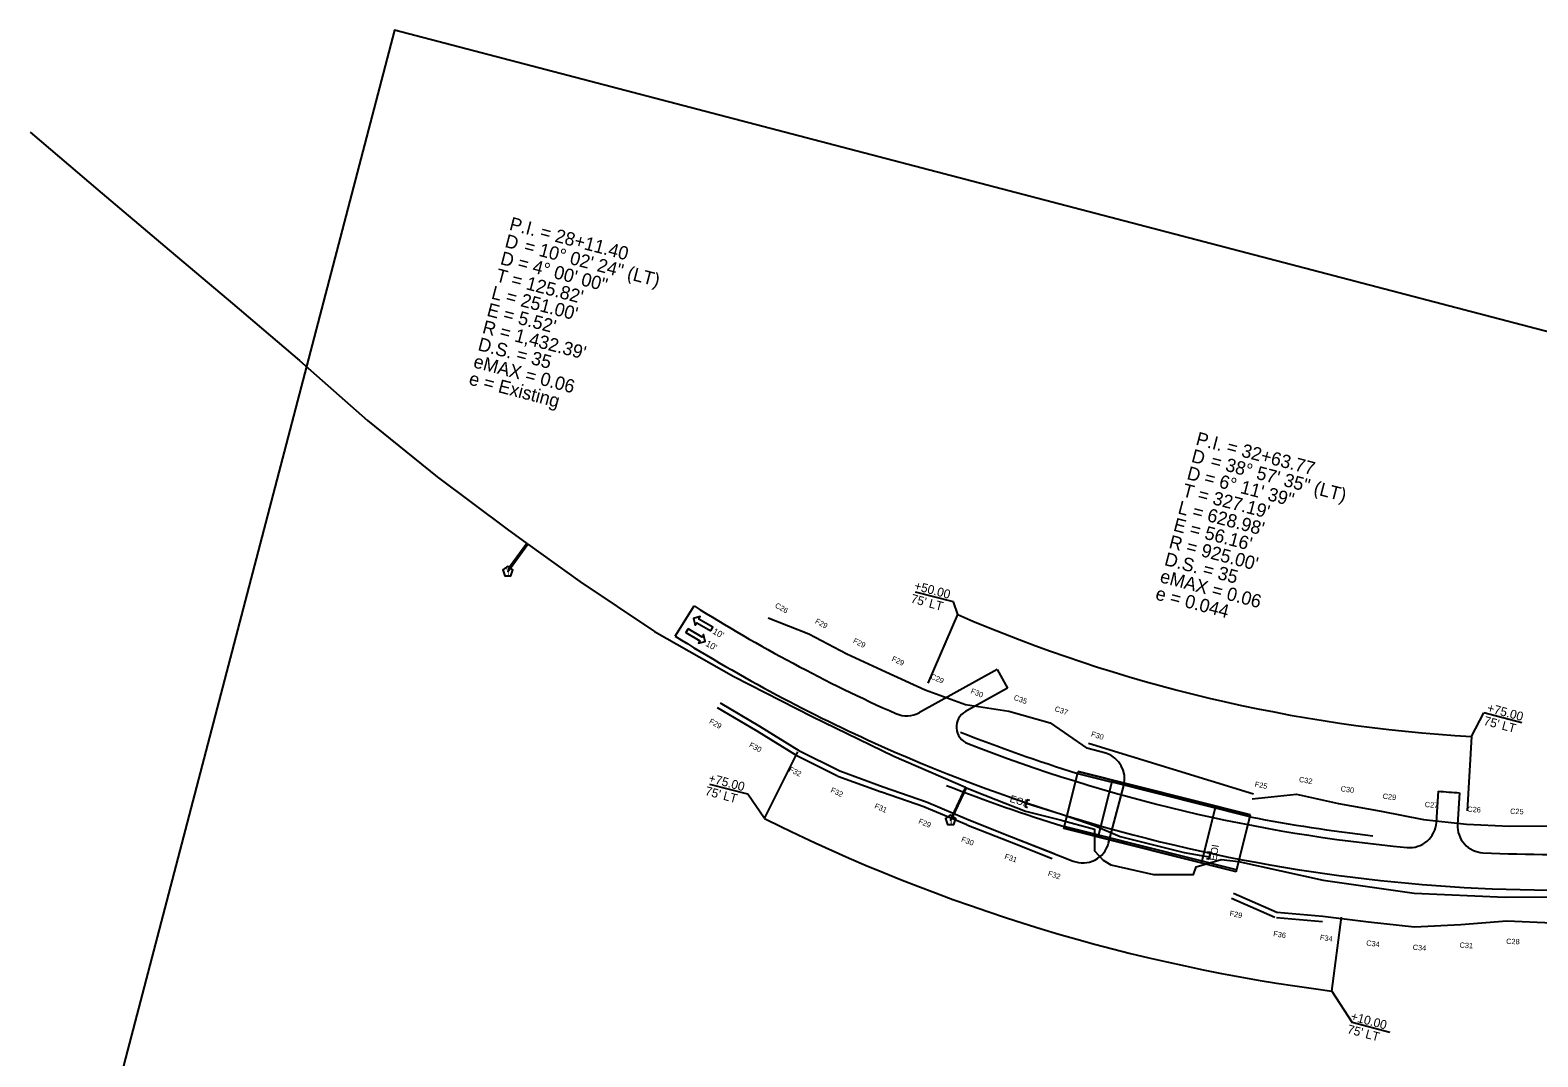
# Model space of a CAD drawing. Extents: x 1749937 to 1751313, y 1197512 to 1198424.
# Drawn here: x 1749937 to 1750785, y 1197847 to 1198424 of the extents above; entities that cross this region are included whole.
import ezdxf

# ---------------------------------------------------------------- set-up
doc = ezdxf.new("R2010")
doc.units = 0
for name, color, linetype in [('Default', 7, 'Continuous'), ('RD_EX_SU_Telecom', 7, 'Continuous'), ('RD_HC_Data', 7, 'Continuous'), ('RD_PD_Bridge', 7, 'Continuous'), ('RD_PD_CstnLmt', 7, 'Continuous'), ('RD_PD_CstnLmt_TX', 7, 'Continuous'), ('RD_PD_DR_ErosCtrl', 7, 'Continuous'), ('RD_PD_Final_TrvlWay', 7, 'Continuous'), ('RD_PD_Final_TX', 7, 'Continuous'), ('RD_PD_GR', 7, 'Continuous'), ('RD_PD_RW', 7, 'Continuous'), ('RD_PD_RW_TX', 7, 'Continuous'), ('RD_SHT_TX', 7, 'Continuous'), ('RD_Sketch8', 7, 'Continuous')]:
    doc.layers.add(name, color=color, linetype=linetype)

msp = doc.modelspace()

# ---------------------------------------------------------------- linework, layer by layer
at = {"layer": 'Default'}
for p, q in [((1750623.49, 1197982.76), (1750526.52, 1198007.16)), ((1750615.44, 1197950.76), (1750518.46, 1197975.16))]:
    msp.add_line(p, q, dxfattribs=at)
at = {"layer": 'RD_EX_SU_Telecom'}
for points in [[(1749936.95, 1198366.88), (1749975.01, 1198334.42), (1750012.72, 1198302.61), (1750050.8, 1198270.5), (1750088.57, 1198238.35), (1750126.73, 1198204.64), (1750165.86, 1198173.01), (1750205.36, 1198143.62), (1750216.46, 1198135.51), (1750206.61, 1198122.08), (1750205.72, 1198119.8), (1750206.99, 1198121.4), (1750217, 1198135.05), (1750246.28, 1198114.18), (1750288.16, 1198086), (1750332.77, 1198060.57), (1750376.88, 1198038.06), (1750422.94, 1198015.85), (1750463.19, 1197998.36), (1750455.48, 1197981.94), (1750454.81, 1197979.82), (1750456.15, 1197981.79), (1750463.75, 1197998.11), (1750468.77, 1197996.03), (1750496.94, 1197984.86), (1750516.41, 1197980.04), (1750535.73, 1197974.84), (1750535.74, 1197962.64), (1750540.69, 1197957.29), (1750544.95, 1197954.73), (1750568.97, 1197949.25), (1750591.43, 1197949.3), (1750593.01, 1197953.62), (1750606.97, 1197957.65), (1750616.7, 1197956.6), (1750664.45, 1197945.99), (1750715.65, 1197938.78), (1750766.73, 1197936.52), (1750806.88, 1197936.68)], [(1750499.33, 1197990.84), (1750497.9, 1197991.29), (1750496.72, 1197987.46), (1750498.15, 1197987.02)], [(1750497.31, 1197989.37), (1750517.19, 1197983.24), (1750536.2, 1197976.71), (1750550.11, 1197970.61), (1750586.21, 1197961.68), (1750595.71, 1197959.95), (1750600.38, 1197959.19)], [(1750599.32, 1197962.03), (1750600.8, 1197961.8), (1750600.17, 1197957.85), (1750598.69, 1197958.09)]]:
    msp.add_lwpolyline(points, dxfattribs=at)
for points in [[(1750205.72, 1198122.8), (1750202.87, 1198120.73), (1750203.96, 1198117.37), (1750207.48, 1198117.37), (1750208.57, 1198120.73)], [(1750454.81, 1197982.82), (1750451.96, 1197980.75), (1750453.05, 1197977.39), (1750456.58, 1197977.39), (1750457.67, 1197980.75)]]:
    msp.add_lwpolyline(points, close=True, dxfattribs=at)
at = {"layer": 'RD_PD_Bridge'}
for p, q in [((1750518.46, 1197975.16), (1750526.52, 1198007.16)), ((1750623.47, 1197982.68), (1750526.5, 1198007.08)), ((1750537.86, 1197970.28), (1750545.91, 1198002.28)), ((1750623.23, 1197981.71), (1750545.65, 1198001.23)), ((1750596.05, 1197955.64), (1750604.1, 1197987.64)), ((1750615.44, 1197950.76), (1750623.49, 1197982.76)), ((1750615.46, 1197950.84), (1750518.49, 1197975.24)), ((1750615.71, 1197951.81), (1750538.12, 1197971.33))]:
    msp.add_line(p, q, dxfattribs=at)
at = {"layer": 'RD_PD_CstnLmt'}
for p, q in [((1750352.25, 1198093.65), (1750374.98, 1198084.64)), ((1750352.25, 1198093.65), (1750374.98, 1198084.64)), ((1750374.98, 1198084.64), (1750396.49, 1198073.49)), ((1750374.98, 1198084.64), (1750396.49, 1198073.49)), ((1750396.49, 1198073.49), (1750418.43, 1198063.23)), ((1750396.49, 1198073.49), (1750418.43, 1198063.23)), ((1750418.43, 1198063.23), (1750440.44, 1198053.14)), ((1750418.43, 1198063.23), (1750440.44, 1198053.14)), ((1750440.44, 1198053.14), (1750463.21, 1198044.84)), ((1750440.44, 1198053.14), (1750463.21, 1198044.84)), ((1750325.09, 1198045.87), (1750347.28, 1198032.66)), ((1750325.09, 1198045.87), (1750347.28, 1198032.66)), ((1750463.21, 1198044.84), (1750487.62, 1198041.11)), ((1750463.21, 1198044.84), (1750487.62, 1198041.11)), ((1750487.62, 1198041.11), (1750510.82, 1198034.65)), ((1750487.62, 1198041.11), (1750510.82, 1198034.65)), ((1750347.28, 1198032.66), (1750369.33, 1198019.04)), ((1750347.28, 1198032.66), (1750369.33, 1198019.04)), ((1750510.82, 1198034.65), (1750531.52, 1198020.37)), ((1750510.82, 1198034.65), (1750531.52, 1198020.37)), ((1750369.33, 1198019.04), (1750392.48, 1198007.49)), ((1750369.33, 1198019.04), (1750392.48, 1198007.49)), ((1750542.23, 1198017.48), (1750531.52, 1198020.37)), ((1750392.48, 1198007.49), (1750416.84, 1197998.64)), ((1750392.48, 1198007.49), (1750416.84, 1197998.64)), ((1750416.84, 1197998.64), (1750441.26, 1197990.15)), ((1750416.84, 1197998.64), (1750441.26, 1197990.15)), ((1750543.73, 1197966.96), (1750552.21, 1197999.39)), ((1750441.26, 1197990.15), (1750465.02, 1197980.08)), ((1750441.26, 1197990.15), (1750465.02, 1197980.08)), ((1750624.38, 1197991.83), (1750649.48, 1197994.47)), ((1750624.38, 1197991.83), (1750649.48, 1197994.47)), ((1750649.48, 1197994.47), (1750673.12, 1197989.2)), ((1750649.48, 1197994.47), (1750673.12, 1197989.2)), ((1750673.12, 1197989.2), (1750696.98, 1197984.98)), ((1750673.12, 1197989.2), (1750696.98, 1197984.98)), ((1750696.98, 1197984.98), (1750720.89, 1197980.28)), ((1750696.98, 1197984.98), (1750720.89, 1197980.28)), ((1750465.02, 1197980.08), (1750489.04, 1197970.54)), ((1750465.02, 1197980.08), (1750489.04, 1197970.54)), ((1750720.89, 1197980.28), (1750745.05, 1197977.56)), ((1750720.89, 1197980.28), (1750745.05, 1197977.56)), ((1750745.05, 1197977.56), (1750769.33, 1197976.37)), ((1750745.05, 1197977.56), (1750769.33, 1197976.37)), ((1750769.33, 1197976.37), (1750793.64, 1197976.67)), ((1750489.04, 1197970.54), (1750523.69, 1197956.81)), ((1750489.04, 1197970.54), (1750513.12, 1197961)), ((1750614.04, 1197938.79), (1750638.39, 1197928.02)), ((1750638.39, 1197928.02), (1750664.29, 1197925.78)), ((1750664.29, 1197925.78), (1750690.01, 1197922.59)), ((1750690.01, 1197922.59), (1750715.78, 1197919.89)), ((1750741.81, 1197921.08), (1750767.72, 1197923.21)), ((1750767.72, 1197923.21), (1750793.47, 1197922.06)), ((1750715.78, 1197919.89), (1750741.81, 1197921.08))]:
    msp.add_line(p, q, dxfattribs=at)
for centre, start, end in [((1750537.69, 1198003.18), 345.34521, 72.38667), ((1750529.21, 1197970.76), 248.38645, 345.34521)]:
    msp.add_arc(centre, 15, start, end, dxfattribs=at)
at = {"layer": 'RD_PD_DR_ErosCtrl'}
for p, q in [((1750323.56, 1198043.29), (1750345.74, 1198030.08)), ((1750345.7, 1198030.11), (1750367.98, 1198016.35)), ((1750367.99, 1198016.36), (1750391.14, 1198004.8)), ((1750532.4, 1198023.24), (1750625.26, 1197994.7)), ((1750391.45, 1198004.67), (1750415.82, 1197995.82)), ((1750415.86, 1197995.8), (1750440.28, 1197987.32)), ((1750440.09, 1197987.39), (1750463.85, 1197977.31)), ((1750463.92, 1197977.29), (1750487.93, 1197967.75)), ((1750487.93, 1197967.75), (1750512.02, 1197958.21)), ((1750612.83, 1197936.04), (1750637.18, 1197925.28)), ((1750638.13, 1197925.03), (1750664.03, 1197922.79))]:
    msp.add_line(p, q, dxfattribs=at)
at = {"layer": 'RD_PD_Final_TrvlWay'}
for p, q in [((1750299.93, 1198083.33), (1750310.5, 1198100.31)), ((1750480.95, 1198064.52), (1750437.39, 1198040.38)), ((1750480.95, 1198064.52), (1750486.77, 1198054.02)), ((1750486.77, 1198054.02), (1750463.24, 1198040.99)), ((1750729.09, 1197996.11), (1750728.08, 1197978.55)), ((1750741.06, 1197995.28), (1750740.03, 1197977.35))]:
    msp.add_line(p, q, dxfattribs=at)
for centre, radius, start, end in [((1750796.56, 1198875.53), 915, 237.91226, 245.97379), ((1750796.56, 1198875.53), 935, 237.91622, 245.97379), ((1750468.09, 1198032.24), 10, 118.98986, 248.71842), ((1750430.12, 1198053.5), 15, 245.97379, 298.98986), ((1750796.56, 1198875.53), 935, 245.97379, 276.93571), ((1750796.56, 1198875.53), 915, 248.71842, 264.67931), ((1750796.56, 1198875.53), 882, 265.61251, 266.39211), ((1750713.11, 1197979.41), 15, 264.67931, 356.71693), ((1750755.01, 1197976.49), 15, 176.71693, 267.35356), ((1750796.56, 1198875.53), 915, 267.35356, 276.93571)]:
    msp.add_arc(centre, radius, start, end, dxfattribs=at)
at = {"layer": 'RD_PD_Final_TX'}
for points in [[(1750319.94, 1198086.38), (1750321.12, 1198088.47), (1750313.13, 1198092.98), (1750313.93, 1198094.39), (1750310.08, 1198093.32), (1750311.15, 1198089.47), (1750311.95, 1198090.89)], [(1750307.08, 1198087.45), (1750305.86, 1198085.38), (1750313.76, 1198080.72), (1750312.93, 1198079.32), (1750316.8, 1198080.31), (1750315.8, 1198084.19), (1750314.98, 1198082.79)]]:
    msp.add_lwpolyline(points, close=True, dxfattribs=at)
at = {"layer": 'RD_PD_GR'}
for p, q in [((1750526.28, 1198006.1), (1750545.65, 1198001.23)), ((1750538.12, 1197971.33), (1750518.61, 1197976.24))]:
    msp.add_line(p, q, dxfattribs=at)
for radius, start, end in [(910.47, 248.32633, 252.73091), (941.26, 248.56342, 252.82482), (910.47, 259.0234, 263.42839)]:
    msp.add_arc((1750796.56, 1198875.53), radius, start, end, dxfattribs=at)
at = {"layer": 'RD_PD_RW'}
for p, q in [((1750442.11, 1198056.98), (1750458.8, 1198095.52)), ((1750747.88, 1198026.92), (1750745.48, 1197984.99)), ((1750350.19, 1197980.68), (1750368.94, 1198018.26)), ((1750669.34, 1197883.65), (1750674.68, 1197925.31))]:
    msp.add_line(p, q, dxfattribs=at)
for radius, start, end in [(850, 246.58597, 266.71692), (1000, 243.4889, 262.69073)]:
    msp.add_arc((1750796.56, 1198875.53), radius, start, end, dxfattribs=at)
at = {"layer": 'RD_PD_RW_TX'}
for p, q in [((1750456.43, 1198102.59), (1750435.14, 1198108.16)), ((1750458.8, 1198095.52), (1750456.43, 1198102.59)), ((1750747.88, 1198026.92), (1750754.81, 1198040.12)), ((1750776.11, 1198034.55), (1750754.81, 1198040.12)), ((1750340.69, 1197994.38), (1750319.39, 1197999.95)), ((1750350.19, 1197980.68), (1750340.69, 1197994.38)), ((1750669.34, 1197883.65), (1750680.7, 1197865.93)), ((1750702, 1197860.36), (1750680.7, 1197865.93))]:
    msp.add_line(p, q, dxfattribs=at)
at = {"layer": 'RD_Sketch8'}
msp.add_lwpolyline([(1749974.91, 1197785.71), (1751019.78, 1197512.48), (1751186.75, 1198151.01), (1750141.89, 1198424.24)], close=True, dxfattribs=at)

# ---------------------------------------------------------------- texts
at = {"layer": 'RD_EX_SU_Telecom'}
for p in [(1750204.49, 1198117.57), (1750453.59, 1197977.59)]:
    msp.add_text('T', height=3.75, dxfattribs=at).set_placement(p)
for rotation, p in [(342.85079, (1750487.77, 1197990.22)), (80.83293, (1750604.35, 1197956.69))]:
    msp.add_text('EOI', height=4, rotation=rotation, dxfattribs=at).set_placement(p)
at = {"layer": 'RD_HC_Data'}
for s, p in [('P.I. = 28+11.40', (1750206.08, 1198312.04)), ('D', (1750203.55, 1198302.36)), ('    = 10%%d 02\' 24" (LT)', (1750203.55, 1198302.36)), ('D = 4%%d 00\' 00"', (1750201.02, 1198292.69)), ("T = 125.82'", (1750198.49, 1198283.01)), ("L = 251.00'", (1750195.96, 1198273.34)), ("E = 5.52'", (1750193.43, 1198263.66)), ("R = 1,432.39'", (1750190.9, 1198253.99)), ('D.S. = 35', (1750188.37, 1198244.31)), ('eMAX = 0.06', (1750185.84, 1198234.64)), ('e = Existing', (1750183.31, 1198224.97)), ('P.I. = 32+63.77', (1750592.33, 1198191.15)), ('D', (1750589.8, 1198181.47)), ('D = 6%%d 11\' 39"', (1750587.27, 1198171.8)), ('    = 38%%d 57\' 35" (LT)', (1750589.8, 1198181.47)), ("T = 327.19'", (1750584.74, 1198162.12)), ("L = 628.98'", (1750582.21, 1198152.45)), ("E = 56.16'", (1750579.68, 1198142.77)), ("R = 925.00'", (1750577.15, 1198133.1)), ('D.S. = 35', (1750574.62, 1198123.42)), ('eMAX = 0.06', (1750572.09, 1198113.75)), ('e = 0.044', (1750569.56, 1198104.07))]:
    msp.add_text(s, height=7.5, rotation=345.34521, dxfattribs=at).set_placement(p)
at = {"layer": 'RD_PD_CstnLmt_TX'}
for s, rotation, p in [('C26', 330.39183, (1750355.71, 1198099.74)), ('F29', 331.94037, (1750378.28, 1198090.82)), ('F29', 333.4889, (1750399.61, 1198079.76)), ('F29', 335.03744, (1750421.38, 1198069.57)), ('C29', 336.58597, (1750443.23, 1198059.56)), ('F30', 338.1345, (1750465.81, 1198051.33)), ('C35', 339.68304, (1750490.05, 1198047.67)), ('C37', 341.23157, (1750513.08, 1198041.28)), ('F29', 330.39183, (1750318.67, 1198034.57)), ('F30', 342.78011, (1750533.59, 1198027.06)), ('F30', 331.94037, (1750341.16, 1198021.19)), ('F32', 333.4889, (1750363.53, 1198007.41)), ('F25', 348.97425, (1750625.72, 1197998.7)), ('C32', 350.52278, (1750650.64, 1198001.37)), ('C30', 352.07132, (1750674.09, 1197996.14)), ('F32', 335.03744, (1750386.99, 1197995.7)), ('C29', 353.61985, (1750697.76, 1197991.94)), ('C27', 355.16839, (1750721.48, 1197987.25)), ('F31', 336.58597, (1750411.68, 1197986.71)), ('C26', 356.71692, (1750745.45, 1197984.55)), ('C25', 358.26546, (1750769.55, 1197983.37)), ('F29', 338.1345, (1750436.42, 1197978.09)), ('F30', 339.68304, (1750460.51, 1197967.88)), ('F31', 341.23157, (1750484.85, 1197958.23)), ('F32', 342.78011, (1750509.27, 1197948.58)), ('F29', 348.97425, (1750611.56, 1197926.03)), ('F36', 350.52278, (1750636.15, 1197914.59)), ('F34', 352.07132, (1750662.44, 1197912.47)), ('C34', 353.61985, (1750688.52, 1197909.32)), ('C34', 355.16839, (1750714.69, 1197906.94)), ('C31', 356.71692, (1750741.07, 1197908.1)), ('C28', 358.26546, (1750767.33, 1197910.21))]:
    msp.add_text(s, height=3, rotation=rotation, dxfattribs=at).set_placement(p)
at = {"layer": 'RD_PD_RW_TX'}
for s, p in [('+50.00', (1750433.96, 1198109.56)), ("75' LT", (1750432.03, 1198102.31)), ('+75.00', (1750756.26, 1198040.84)), ("75' LT", (1750754.34, 1198033.59)), ("75' LT", (1750316.29, 1197994.1)), ('+75.00', (1750318.22, 1198001.35)), ("75' LT", (1750677.6, 1197860.08)), ('+10.00', (1750679.52, 1197867.33))]:
    msp.add_text(s, height=5, rotation=345.13739, dxfattribs=at).set_placement(p)
at = {"layer": 'RD_SHT_TX'}
for p in [(1750320.54, 1198084.96), (1750316.63, 1198078.07)]:
    msp.add_text("10'", height=3.6, rotation=331.43524, dxfattribs=at).set_placement(p)

doc.saveas('drawing.dxf')
